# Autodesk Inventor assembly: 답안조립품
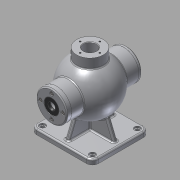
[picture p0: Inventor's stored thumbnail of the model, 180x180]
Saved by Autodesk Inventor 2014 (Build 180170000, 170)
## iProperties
Created: 2015-10
Part Number: 답안조립품
Document SubType Name: Assembly
Designer: youjin10
Author: youjin10
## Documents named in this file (6)
- C:\Users\youjin10\Desktop\451010V1008\답안조립품.iam
- C:\Users\youjin10\Desktop\451010V1008\본체.ipt
- C:\Users\youjin10\Desktop\451010V1008\앞커버.ipt
- C:\Users\youjin10\Desktop\451010V1008\볼트 M4 x 16.ipt
- C:\Users\youjin10\Desktop\451010V1008\오일실 15 30 7.ipt
- C:\Users\youjin10\Desktop\451010V1008\뒤커버.ipt
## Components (8 placed, 1 different names)
1. ISO 4762 M4 x 16:1 — Insert:1
2. ISO 4762 M4 x 16:2
3. ISO 4762 M4 x 16:3
4. ISO 4762 M4 x 16:4
5. ISO 4762 M4 x 16:5 — Insert:2
6. ISO 4762 M4 x 16:6
7. ISO 4762 M4 x 16:7
8. ISO 4762 M4 x 16:8
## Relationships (2: Insert 2)
- Insert:1: ISO 4762 M4 x 16:1
- Insert:2: ISO 4762 M4 x 16:5
